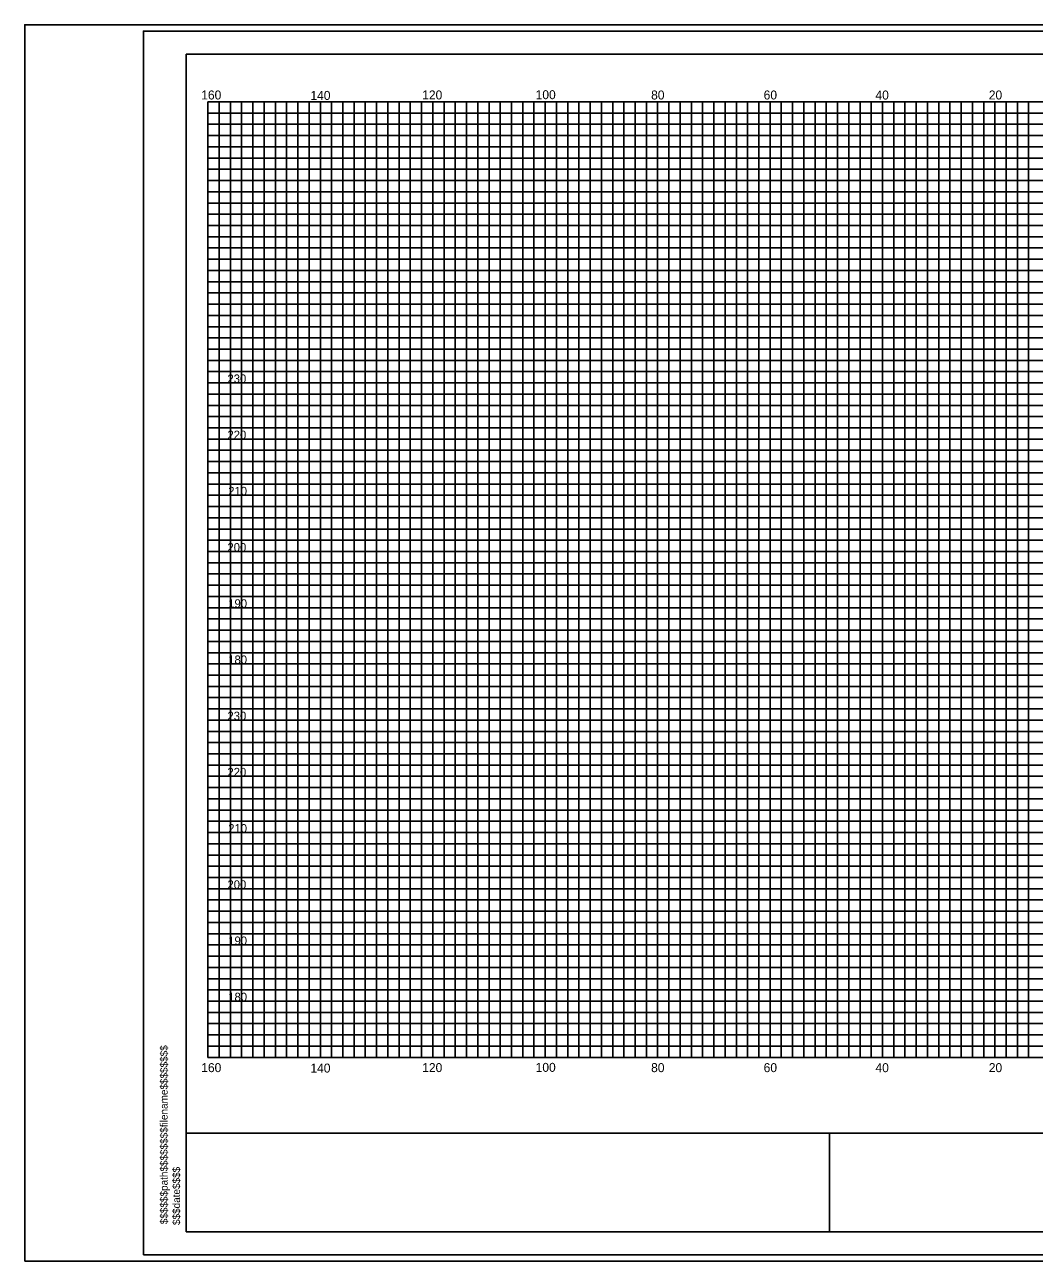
# Model space of a CAD drawing. Extents: x 967 to 1746, y 964 to 7904.
# Drawn here: x 967.4 to 1147, y 4323.7 to 4543.7 of the extents above; entities that cross this region are included whole.
import ezdxf

# ---------------------------------------------------------------- set-up
doc = ezdxf.new("R2010")
doc.units = 0
for name, color, linetype in [('Default', 7, 'Continuous'), ('RD_SHT_Bndy', 7, 'Continuous'), ('RD_SHT_IplotShp', 7, 'Continuous'), ('RD_SHT_MjGrid', 7, 'Continuous'), ('RD_SHT_MnGrid', 7, 'Continuous'), ('RD_SHT_TX', 7, 'Continuous'), ('RD_Sketch1', 7, 'Continuous')]:
    doc.layers.add(name, color=color, linetype=linetype)

msp = doc.modelspace()

# ---------------------------------------------------------------- linework, layer by layer
at = {"layer": 'RD_SHT_Bndy'}
for p, q in [((996.11, 4328.98), (996.11, 4538.46)), ((996.11, 4538.46), (1323.89, 4538.46)), ((996.11, 4346.49), (1323.89, 4346.49)), ((1110.59, 4328.98), (1110.59, 4346.56)), ((1323.89, 4328.98), (996.11, 4328.98))]:
    msp.add_line(p, q, dxfattribs=at)
at = {"layer": 'RD_SHT_IplotShp'}
for points in [[(967.41, 4323.72), (1326.28, 4323.72), (1326.28, 4543.72), (967.41, 4543.72)], [(988.52, 4324.84), (1326.28, 4324.84), (1326.28, 4542.6), (988.52, 4542.6)]]:
    msp.add_lwpolyline(points, close=True, dxfattribs=at)
at = {"layer": 'RD_SHT_MjGrid'}
for p, q in [((1000, 4530), (1320, 4530)), ((1000, 4360), (1000, 4530)), ((1010, 4360), (1010, 4530)), ((1020, 4360), (1020, 4530)), ((1030, 4360), (1030, 4530)), ((1040, 4360), (1040, 4530)), ((1050, 4360), (1050, 4530)), ((1060, 4360), (1060, 4530)), ((1070, 4360), (1070, 4530)), ((1080, 4360), (1080, 4530)), ((1090, 4360), (1090, 4530)), ((1100, 4360), (1100, 4530)), ((1110, 4360), (1110, 4530)), ((1120, 4360), (1120, 4530)), ((1130, 4360), (1130, 4530)), ((1140, 4360), (1140, 4530)), ((1000, 4520), (1320, 4520)), ((1000, 4510), (1320, 4510)), ((1000, 4500), (1320, 4500)), ((1000, 4490), (1320, 4490)), ((1000, 4480), (1320, 4480)), ((1000, 4470), (1320, 4470)), ((1000, 4460), (1320, 4460)), ((1000, 4450), (1320, 4450)), ((1000, 4440), (1320, 4440)), ((1000, 4430), (1320, 4430)), ((1000, 4420), (1320, 4420)), ((1000, 4410), (1320, 4410)), ((1000, 4400), (1320, 4400)), ((1000, 4390), (1320, 4390)), ((1000, 4380), (1320, 4380)), ((1000, 4370), (1320, 4370)), ((1000, 4360), (1320, 4360))]:
    msp.add_line(p, q, dxfattribs=at)
at = {"layer": 'RD_SHT_MnGrid'}
for p, q in [((1002, 4360), (1002, 4530)), ((1004, 4360), (1004, 4530)), ((1006, 4360), (1006, 4530)), ((1008, 4360), (1008, 4530)), ((1012, 4360), (1012, 4530)), ((1014, 4360), (1014, 4530)), ((1016, 4360), (1016, 4530)), ((1018, 4360), (1018, 4530)), ((1022, 4360), (1022, 4530)), ((1024, 4360), (1024, 4530)), ((1026, 4360), (1026, 4530)), ((1028, 4360), (1028, 4530)), ((1032, 4360), (1032, 4530)), ((1034, 4360), (1034, 4530)), ((1036, 4360), (1036, 4530)), ((1038, 4360), (1038, 4530)), ((1042, 4360), (1042, 4530)), ((1044, 4360), (1044, 4530)), ((1046, 4360), (1046, 4530)), ((1048, 4360), (1048, 4530)), ((1052, 4360), (1052, 4530)), ((1054, 4360), (1054, 4530)), ((1056, 4360), (1056, 4530)), ((1058, 4360), (1058, 4530)), ((1062, 4360), (1062, 4530)), ((1064, 4360), (1064, 4530)), ((1066, 4360), (1066, 4530)), ((1068, 4360), (1068, 4530)), ((1072, 4360), (1072, 4530)), ((1074, 4360), (1074, 4530)), ((1076, 4360), (1076, 4530)), ((1078, 4360), (1078, 4530)), ((1082, 4360), (1082, 4530)), ((1084, 4360), (1084, 4530)), ((1086, 4360), (1086, 4530)), ((1088, 4360), (1088, 4530)), ((1092, 4360), (1092, 4530)), ((1094, 4360), (1094, 4530)), ((1096, 4360), (1096, 4530)), ((1098, 4360), (1098, 4530)), ((1102, 4360), (1102, 4530)), ((1104, 4360), (1104, 4530)), ((1106, 4360), (1106, 4530)), ((1108, 4360), (1108, 4530)), ((1112, 4360), (1112, 4530)), ((1114, 4360), (1114, 4530)), ((1116, 4360), (1116, 4530)), ((1118, 4360), (1118, 4530)), ((1122, 4360), (1122, 4530)), ((1124, 4360), (1124, 4530)), ((1126, 4360), (1126, 4530)), ((1128, 4360), (1128, 4530)), ((1132, 4360), (1132, 4530)), ((1134, 4360), (1134, 4530)), ((1136, 4360), (1136, 4530)), ((1138, 4360), (1138, 4530)), ((1142, 4360), (1142, 4530)), ((1144, 4360), (1144, 4530)), ((1146, 4360), (1146, 4530)), ((1000, 4528), (1320, 4528)), ((1000, 4526), (1320, 4526)), ((1000, 4524), (1320, 4524)), ((1000, 4522), (1320, 4522)), ((1000, 4518), (1320, 4518)), ((1000, 4516), (1320, 4516)), ((1000, 4514), (1320, 4514)), ((1000, 4512), (1320, 4512)), ((1000, 4508), (1320, 4508)), ((1000, 4506), (1320, 4506)), ((1000, 4504), (1320, 4504)), ((1000, 4502), (1320, 4502)), ((1000, 4498), (1320, 4498)), ((1000, 4496), (1320, 4496)), ((1000, 4494), (1320, 4494)), ((1000, 4492), (1320, 4492)), ((1000, 4488), (1320, 4488)), ((1000, 4486), (1320, 4486)), ((1000, 4484), (1320, 4484)), ((1000, 4482), (1320, 4482)), ((1000, 4478), (1320, 4478)), ((1000, 4476), (1320, 4476)), ((1000, 4474), (1320, 4474)), ((1000, 4472), (1320, 4472)), ((1000, 4468), (1320, 4468)), ((1000, 4466), (1320, 4466)), ((1000, 4464), (1320, 4464)), ((1000, 4462), (1320, 4462)), ((1000, 4458), (1320, 4458)), ((1000, 4456), (1320, 4456)), ((1000, 4454), (1320, 4454)), ((1000, 4452), (1320, 4452)), ((1000, 4448), (1320, 4448)), ((1000, 4446), (1320, 4446)), ((1000, 4444), (1320, 4444)), ((1000, 4442), (1320, 4442)), ((1000, 4438), (1320, 4438)), ((1000, 4436), (1320, 4436)), ((1000, 4434), (1320, 4434)), ((1000, 4432), (1320, 4432)), ((1000, 4428), (1320, 4428)), ((1000, 4426), (1320, 4426)), ((1000, 4424), (1320, 4424)), ((1000, 4422), (1320, 4422)), ((1000, 4418), (1320, 4418)), ((1000, 4416), (1320, 4416)), ((1000, 4414), (1320, 4414)), ((1000, 4412), (1320, 4412)), ((1000, 4408), (1320, 4408)), ((1000, 4406), (1320, 4406)), ((1000, 4404), (1320, 4404)), ((1000, 4402), (1320, 4402)), ((1000, 4398), (1320, 4398)), ((1000, 4396), (1320, 4396)), ((1000, 4394), (1320, 4394)), ((1000, 4392), (1320, 4392)), ((1000, 4388), (1320, 4388)), ((1000, 4386), (1320, 4386)), ((1000, 4384), (1320, 4384)), ((1000, 4382), (1320, 4382)), ((1000, 4378), (1320, 4378)), ((1000, 4376), (1320, 4376)), ((1000, 4374), (1320, 4374)), ((1000, 4372), (1320, 4372)), ((1000, 4368), (1320, 4368)), ((1000, 4366), (1320, 4366)), ((1000, 4364), (1320, 4364)), ((1000, 4362), (1320, 4362))]:
    msp.add_line(p, q, dxfattribs=at)
at = {"layer": 'RD_Sketch1'}
msp.add_lwpolyline([(967.41, 4323.72), (1326.28, 4323.72), (1326.28, 4543.72), (967.41, 4543.72)], close=True, dxfattribs=at)

# ---------------------------------------------------------------- texts
at = {"layer": 'Default'}
for s, p in [('230', (1003.47, 4480)), ('220', (1003.47, 4470)), ('210', (1003.61, 4460)), ('200', (1003.47, 4450)), ('190', (1003.61, 4440)), ('180', (1003.61, 4430)), ('230', (1003.47, 4420)), ('220', (1003.47, 4410)), ('210', (1003.61, 4400)), ('200', (1003.47, 4390)), ('190', (1003.61, 4380)), ('180', (1003.61, 4370))]:
    msp.add_text(s, height=1.5, dxfattribs=at).set_placement(p)
for s, p in [('$$$$$$path$$$$$$$$filename$$$$$$$$', (992.83, 4330.31)), ('$$$date$$$$', (995.04, 4330.17))]:
    msp.add_text(s, height=1.3258, rotation=90, dxfattribs=at).set_placement(p)
at = {"layer": 'RD_SHT_TX'}
for s, p in [('160', (998.81, 4530.42)), ('120', (1038.12, 4530.43)), ('100', (1058.3, 4530.47)), ('80', (1078.84, 4530.42)), ('60', (1098.86, 4530.42)), ('40', (1118.75, 4530.41)), ('20', (1138.91, 4530.42)), ('140', (1018.23, 4530.34)), ('160', (998.81, 4357.37)), ('140', (1018.23, 4357.29)), ('120', (1038.12, 4357.38)), ('100', (1058.3, 4357.42)), ('80', (1078.84, 4357.37)), ('60', (1098.86, 4357.37)), ('40', (1118.75, 4357.36)), ('20', (1138.91, 4357.37))]:
    msp.add_text(s, height=1.6, dxfattribs=at).set_placement(p)

doc.saveas('drawing.dxf')
